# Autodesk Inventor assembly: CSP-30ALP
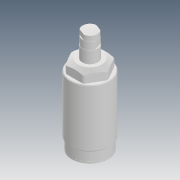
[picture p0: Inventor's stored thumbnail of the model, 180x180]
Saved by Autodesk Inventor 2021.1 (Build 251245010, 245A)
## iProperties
Created: 2019-01
Part Number: CSP-30ALP
Description: STEP AP203
Document SubType Name: Assembly
Designer: user
Title: CSP-030-P×é×°Í¼£¨ÉÏÉý×´Ì¬£©.STEP
Revision Number: ÈÎºÎ
Sending System: SolidWorks 2014
Preprocessor: SwSTEP 2.0
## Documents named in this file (4)
- D:\Vault_2016\Projekty\Clamptek\Hydraulic\CSP-P-K\CSP-30KP\Inventor\CSP-30ALP\CSP-30ALP.iam
- D:\Vault_2016\Projekty\Clamptek\Hydraulic\CSP-P-K\CSP-30KP\Inventor\CSP-30ALP\CSP-030-P±¾Ìå£¨ÉÏÉý£©.ipt
- D:\Vault_2016\Projekty\Clamptek\Hydraulic\CSP-P-K\CSP-30KP\Inventor\CSP-30ALP\CSP-030»îÈû¸Ë.ipt
- D:\Vault_2016\Projekty\Clamptek\Hydraulic\CSP-P-K\CSP-30KP\Inventor\CSP-30ALP\CSP-030Ô²Í·ÂÝË¨.ipt
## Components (3 placed, 3 different names)
1. CSP-030-P±¾Ìå£¨ÉÏÉý£©_1
2. CSP-030»îÈû¸Ë_2
3. CSP-030Ô²Í·ÂÝË¨_3
